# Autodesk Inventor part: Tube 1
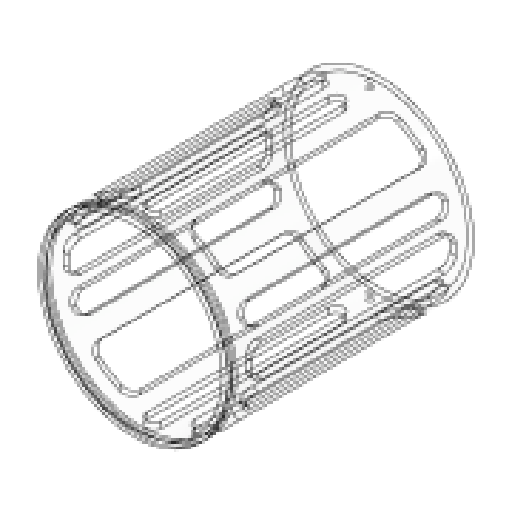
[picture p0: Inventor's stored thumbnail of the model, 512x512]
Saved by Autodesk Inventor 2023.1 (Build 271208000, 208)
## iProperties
Created: 2020-02
Part Number: Tube 1
Material: Polycarbonate, Clear
Document SubType Name: Modeling
Designer: ftrauzettel
Density: 1.2 g/cm^3
Appearance: Polycarbonate - Clear
Sending System: SolidWorks 2016
Last Author: Pam
Last Saved: 2020-07-21
Author: ftrauzettel
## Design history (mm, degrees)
fillet "Fillet1"
body "Solid1"
